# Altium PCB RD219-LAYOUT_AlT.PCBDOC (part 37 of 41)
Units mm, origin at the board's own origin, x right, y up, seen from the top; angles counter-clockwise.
Board outline 209.75 x 159.97 mm, 2 copper layers (TOP, BOTTOM), stack 0 mm thick; 398 components, 199 nets, 1469 pads, 0 vias.
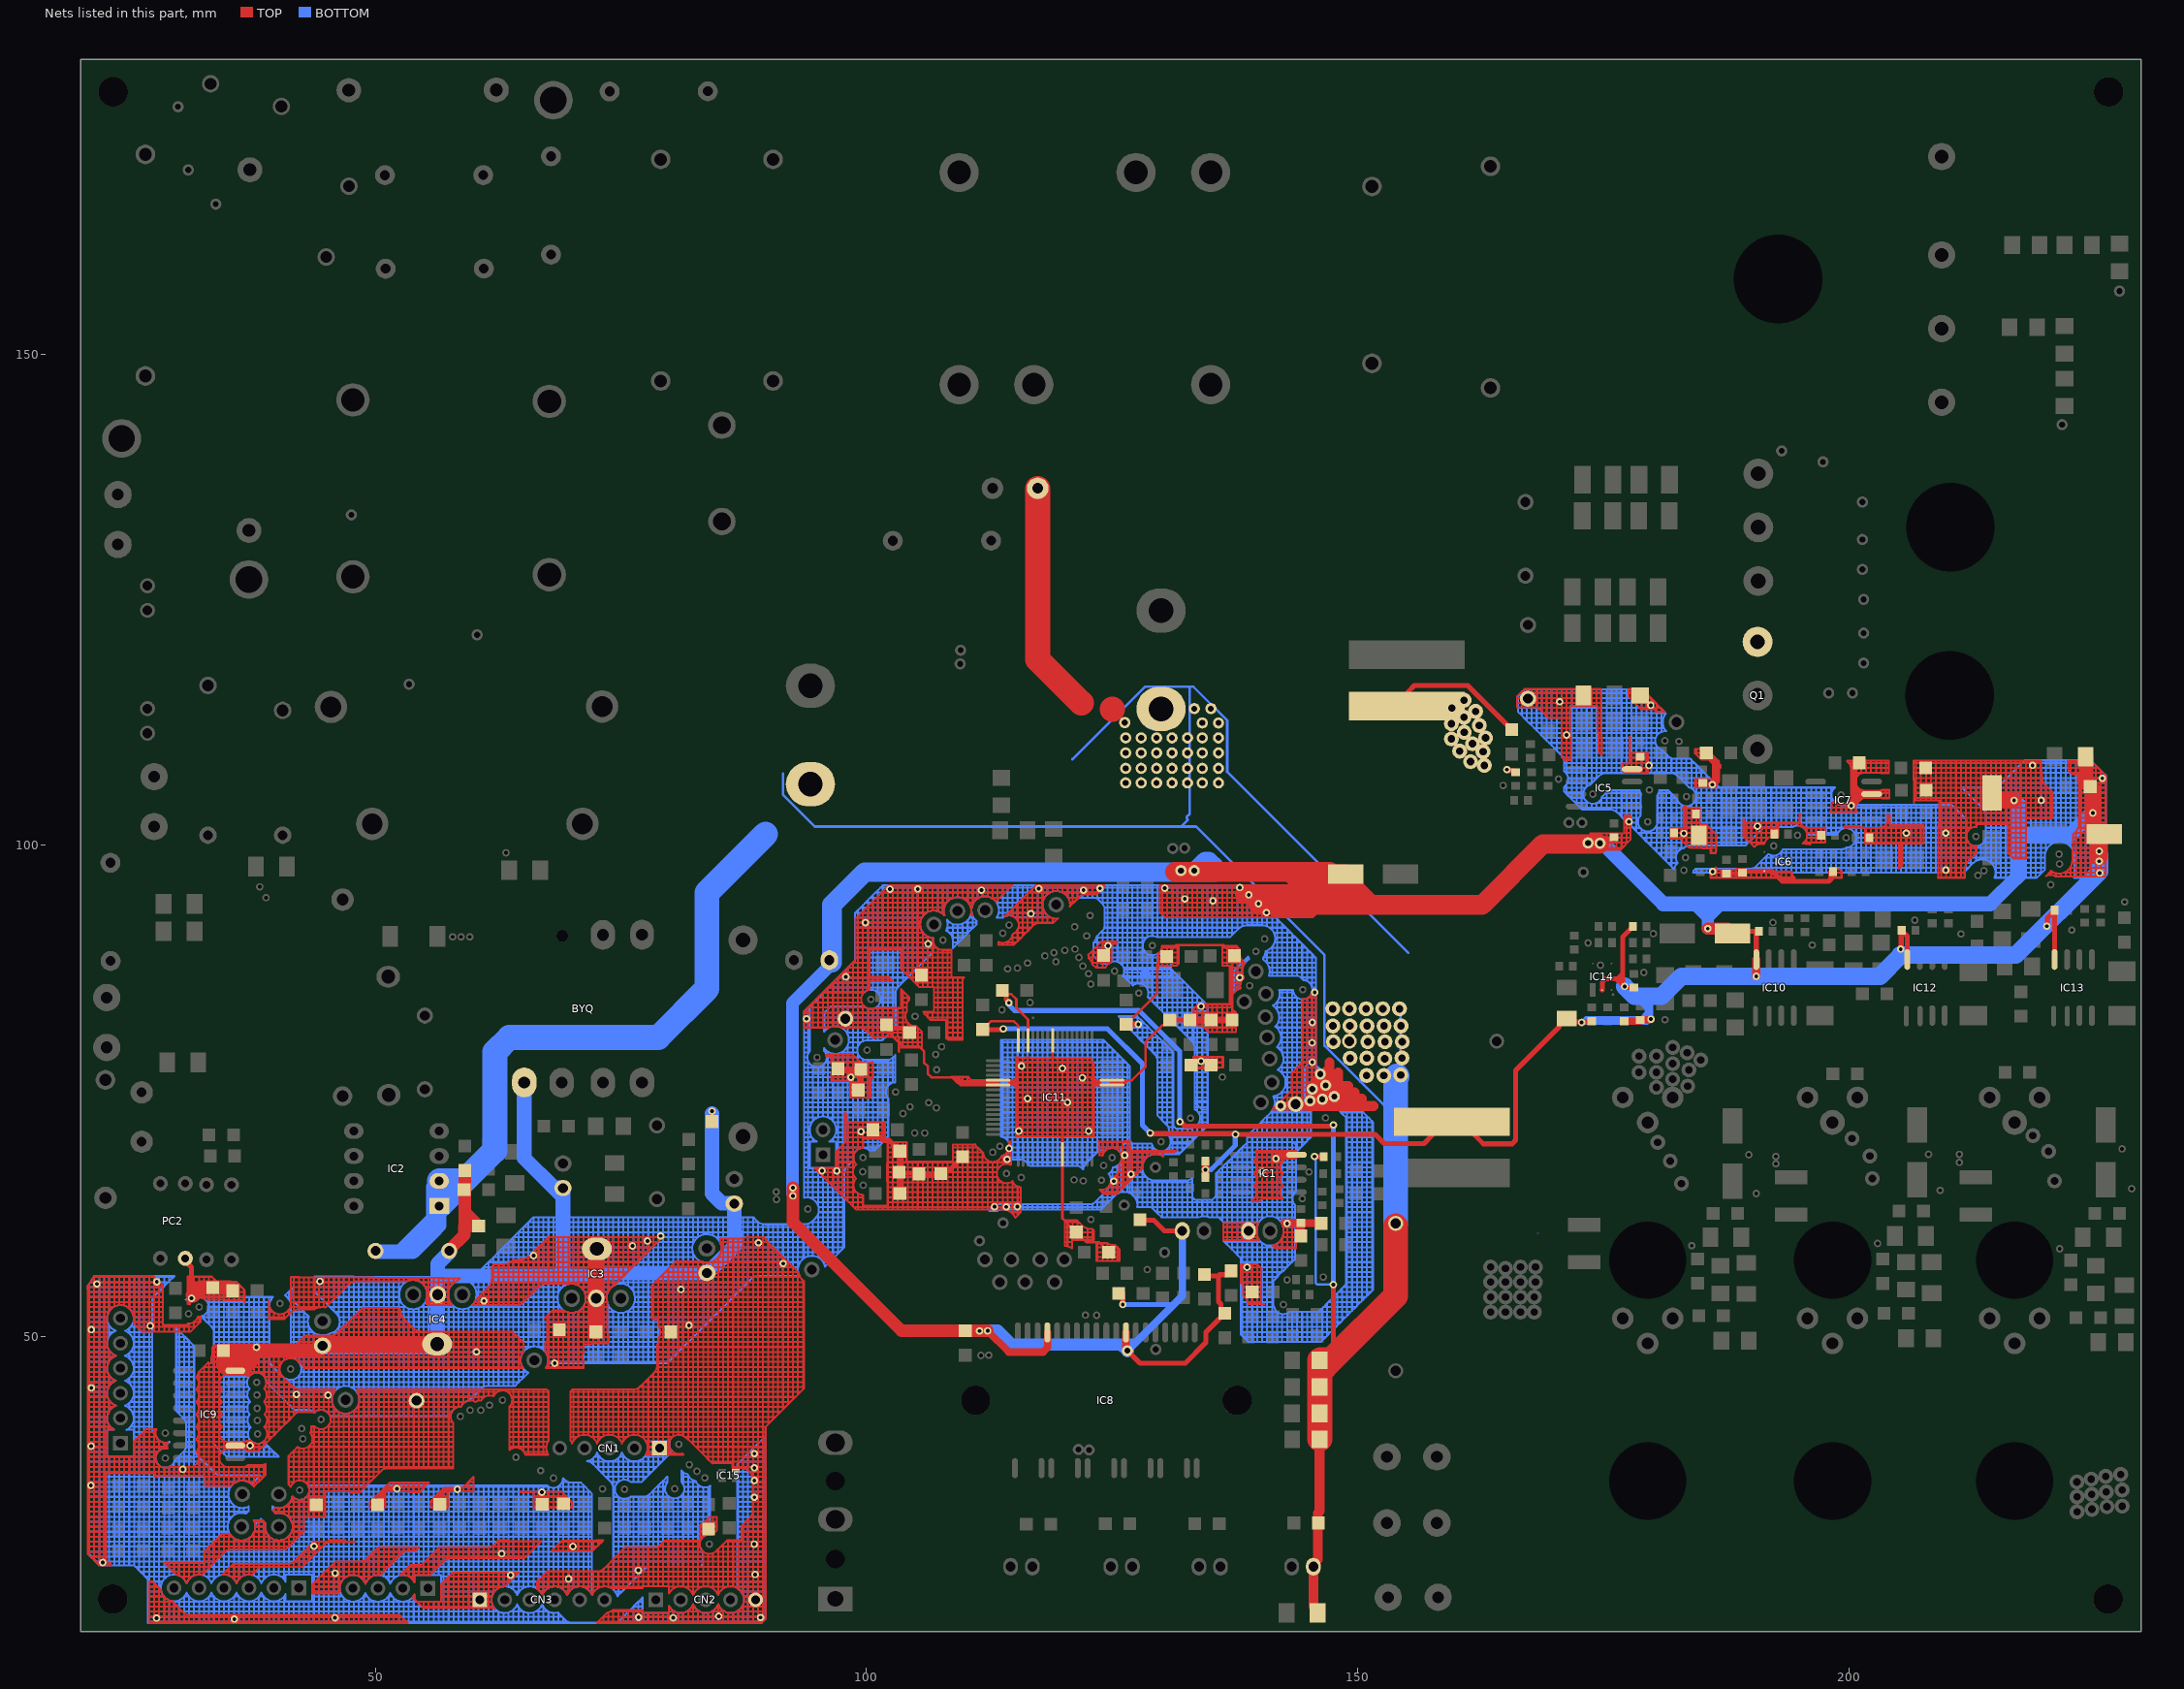
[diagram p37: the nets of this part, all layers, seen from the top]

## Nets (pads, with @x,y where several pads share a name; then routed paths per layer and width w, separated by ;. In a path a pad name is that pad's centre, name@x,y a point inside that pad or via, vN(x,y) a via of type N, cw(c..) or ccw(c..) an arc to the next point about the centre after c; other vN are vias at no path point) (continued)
GND: (continued)
  BOTTOM w0.203: 188.529,97.212 188.529,97.216 ; 188.529,97.212 189.037,97.212 ; 188.529,97.216 188.529,97.63 ; 188.529,97.216 189.037,97.216 ; 188.529,97.63 189.037,97.63 ; 188.529,99.977 188.529,100.264 ; 188.529,99.977 189.037,99.977 ; 188.529,100.264 188.529,100.772 ; 188.529,100.264 189.037,100.264 ; 188.529,100.772 188.529,101.28 ; 188.529,100.772 189.037,100.772 ; 188.529,101.28 188.529,101.788 ; 188.529,101.28 189.037,101.28 ; 188.529,101.788 188.529,102.296 ; 188.529,101.788 189.037,101.788 ; 188.529,102.296 188.529,102.804 ; 188.529,102.296 189.037,102.296 ; 188.529,102.804 188.529,103.312 ; 188.529,102.804 189.037,102.804 ; 188.529,103.312 188.529,103.82 ; 188.529,103.312 189.037,103.312 ; 188.529,103.82 188.529,104.328 ; 188.529,103.82 189.037,103.82 ; 188.529,104.328 188.529,104.836 ; 188.529,104.328 189.037,104.328 ; 188.529,104.836 188.529,105.344 ; 188.529,104.836 189.037,104.836 ; 188.529,105.344 188.529,105.852 ; 188.529,105.344 189.037,105.344 ; 188.529,105.852 188.529,105.886 ; 188.529,105.852 189.037,105.852 ; 188.529,105.886 189.037,105.886 ; 189.037,97.212 189.037,97.216 ; 189.037,97.212 189.545,97.212 ; 189.037,97.216 189.037,97.63 ; 189.037,97.216 189.545,97.216 ; 189.037,97.63 189.545,97.63 ; 189.037,99.977 189.037,100.264 ; 189.037,99.977 189.445,99.977 189.545,100.077 ; 189.037,100.264 189.037,100.772 ; 189.037,100.264 189.545,100.264 ; 189.037,100.772 189.037,101.28 ; 189.037,100.772 189.545,100.772 ; 189.037,101.28 189.037,101.788 ; 189.037,101.28 189.545,101.28 ; 189.037,101.788 189.037,102.296 ; 189.037,101.788 189.545,101.788 ; 189.037,102.296 189.545,102.296 ; 189.037,102.296 189.037,102.804 ; 189.037,102.804 189.545,102.804 ; 189.037,102.804 189.037,103.312 ; 189.037,103.312 189.037,103.82 ; 189.037,103.312 189.545,103.312 ; 189.037,103.82 189.037,104.328 ; 189.037,103.82 189.545,103.82 ; 189.037,104.328 189.545,104.328 ; 189.037,104.328 189.037,104.836 ; 189.037,104.836 189.545,104.836 ; 189.037,104.836 189.037,105.344 ; 189.037,105.344 189.037,105.852 ; 189.037,105.344 189.545,105.344 ; 189.037,105.852 189.545,105.852 ; 189.037,105.852 189.037,105.886 ; 189.037,105.886 189.545,105.886 ; 189.545,97.212 190.053,97.212 ; 189.545,97.212 189.545,97.216 ; 189.545,97.216 190.053,97.216 ; 189.545,97.216 189.545,97.63 ; 189.545,97.63 190.002,97.63 ; 189.545,100.077 189.732,100.264 ; 189.545,100.077 189.545,100.264 ; 189.545,100.264 189.545,100.772 ; 189.545,100.264 189.732,100.264 ; 189.545,100.772 189.545,101.28 ; 189.545,100.772 190.053,100.772 ; 189.545,101.28 189.545,101.788 ; 189.545,101.28 190.053,101.28 ; 189.545,101.788 189.545,102.296 ; 189.545,101.788 190.053,101.788 ; 189.545,102.296 189.545,102.804 ; 189.545,102.296 190.053,102.296 ; 189.545,102.804 189.545,103.312 ; 189.545,102.804 190.053,102.804 ; 189.545,103.312 189.545,103.82 ; 189.545,103.312 190.053,103.312 ; 189.545,103.82 189.545,104.328 ; 189.545,103.82 190.053,103.82 ; 189.545,104.328 190.053,104.328 ; 189.545,104.328 189.545,104.836 ; 189.545,104.836 190.053,104.836 ; 189.545,104.836 189.545,105.344 ; 189.545,105.344 189.545,105.852 ; 189.545,105.344 190.053,105.344 ; 189.545,105.852 190.053,105.852 ; 189.545,105.852 189.545,105.886 ; 189.545,105.886 190.053,105.886 ; 189.732,100.264 190.053,100.585 ; 190.002,97.63 ccw(c190.002,98.359) 190.053,97.632 ; 190.002,97.63 ccw(c190.002,98.359) 190.053,97.632 ; 190.053,97.212 190.053,97.216 ; 190.053,97.212 190.561,97.212 ; 190.053,97.216 190.561,97.216 ; 190.053,97.216 190.053,97.632 ; 190.053,97.632 ccw(c190.002,98.359) 190.359,97.724 ; 190.053,97.632 ccw(c190.002,98.359) 190.359,97.724 ; 190.053,100.585 190.24,100.772 ; 190.053,100.585 190.053,100.772 ; 190.053,100.772 190.053,101.28 ; 190.053,100.772 190.24,100.772 ; 190.053,101.28 190.053,101.788 ; 190.053,101.28 190.561,101.28 ; 190.053,101.788 190.053,102.296 ; 190.053,101.788 pad.@190.561,101.788 ; 190.053,102.296 190.053,102.804 ; 190.053,102.296 pad.@190.561,102.296 ; 190.053,102.804 190.053,103.312 ; 190.053,102.804 190.561,102.804 ; 190.053,103.312 190.053,103.82 ; 190.053,103.312 190.561,103.312 ; 190.053,103.82 190.053,104.328 ; 190.053,103.82 190.561,103.82 ; 190.053,104.328 190.053,104.836 ; 190.053,104.328 190.561,104.328 ; 190.053,104.836 190.053,105.344 ; 190.053,104.836 190.561,104.836 ; 190.053,105.344 190.053,105.852 ; 190.053,105.344 190.561,105.344 ; 190.053,105.852 190.053,105.886 ; 190.053,105.852 190.561,105.852 ; 190.053,105.886 190.561,105.886 ; 190.24,100.772 190.561,101.093 ; 190.359,97.724 ccw(c190.002,98.359) 190.517,97.844 ; 190.359,97.724 ccw(c190.002,98.359) 190.517,97.844 ; 190.359,97.724 190.561,97.724 ; 190.517,97.844 190.905,98.232 ; 190.561,97.212 190.561,97.216 ; 190.561,97.212 191.069,97.212 ; 190.561,97.216 190.561,97.724 ; 190.561,97.216 191.069,97.216 ; 190.561,97.724 191.069,97.724 ; 190.561,101.093 190.748,101.28 ; 190.561,101.093 190.561,101.28 ; 190.561,101.28 pad.@190.561,101.788 ; 190.561,101.28 190.748,101.28 ; pad.@190.561,101.788 191.069,101.788 ; pad.@190.561,101.788 pad.@190.561,102.296 ; pad.@190.561,102.296 190.561,102.804 ; pad.@190.561,102.296 191.069,102.296 ; 190.561,102.804 191.069,102.804 ; 190.561,102.804 190.561,103.312 ; 190.561,103.312 190.561,103.82 ; 190.561,103.312 191.069,103.312 ; 190.561,103.82 190.561,104.328 ; 190.561,103.82 191.069,103.82 ; 190.561,104.328 191.069,104.328 ; 190.561,104.328 190.561,104.836 ; 190.561,104.836 191.069,104.836 ; 190.561,104.836 190.561,105.344 ; 190.561,105.344 190.561,105.852 ; 190.561,105.344 191.069,105.344 ; 190.561,105.852 191.069,105.852 ; 190.561,105.852 190.561,105.886 ; 190.561,105.886 191.069,105.886 ; 190.748,101.28 191.069,101.601 ; 190.905,98.232 191.069,98.396 ; 190.905,98.232 191.069,98.232 ; 191.069,97.212 191.069,97.216 ; 191.069,97.212 191.577,97.212 ; 191.069,97.216 191.069,97.724 ; 191.069,97.216 191.577,97.216 ; 191.069,97.724 191.069,98.232 ; 191.069,97.724 191.577,97.724 ; 191.069,98.232 191.069,98.396 ; 191.069,98.232 191.577,98.232 ; 191.069,98.396 191.413,98.74 ; 191.069,101.601 191.069,101.788 ; 191.069,101.601 191.099,101.631 ; 191.069,101.788 191.315,101.788 ; 191.069,101.788 191.069,102.296 ; 191.069,102.296 191.069,102.804 ; 191.069,102.296 191.577,102.296 ; 191.069,102.804 191.069,103.312 ; 191.069,102.804 191.577,102.804 ; 191.069,103.312 191.069,103.82 ; 191.069,103.312 191.577,103.312 ; 191.069,103.82 191.069,104.328 ; 191.069,103.82 191.577,103.82 ; 191.069,104.328 191.577,104.328 ; 191.069,104.328 191.069,104.836 ; 191.069,104.836 191.577,104.836 ; 191.069,104.836 191.069,105.344 ; 191.069,105.344 191.069,105.852 ; 191.069,105.344 191.577,105.344 ; 191.069,105.852 191.577,105.852 ; 191.069,105.852 191.069,105.886 ; 191.069,105.886 191.577,105.886 ; 191.099,101.631 cw(c191.704,101.026) 191.315,101.788 ; 191.099,101.631 cw(c191.704,101.026) 191.315,101.788 ; 191.316,101.788 cw(c191.704,101.026) 191.577,101.872 ; 191.316,101.788 cw(c191.704,101.026) 191.577,101.872 ; 191.413,98.74 191.577,98.904 ; 191.413,98.74 191.577,98.74 ; 191.577,97.212 191.577,97.216 ; 191.577,97.212 192.085,97.212 ; 191.577,97.216 191.577,97.724 ; 191.577,97.216 192.085,97.216 ; 191.577,97.724 191.577,98.232 ; 191.577,97.724 192.085,97.724 ; 191.577,98.232 191.577,98.74 ; 191.577,98.232 192.085,98.232 ; 191.577,98.74 191.577,98.904 ; 191.577,98.74 192.085,98.74 ; 191.577,101.872 cw(c191.704,101.026) 191.704,101.882 ; 191.577,101.872 cw(c191.704,101.026) 191.704,101.882 ; 191.577,101.872 191.577,102.296 ; 191.577,102.296 191.577,102.804 ; 191.577,102.296 192.085,102.296 ; 191.577,102.804 191.577,103.312 ; 191.577,102.804 192.085,102.804 ; 191.577,103.312 191.577,103.82 ; 191.577,103.312 192.085,103.312 ; 191.577,103.82 191.577,104.328 ; 191.577,103.82 192.085,103.82 ; 191.577,104.328 192.085,104.328 ; 191.577,104.328 191.577,104.836 ; 191.577,104.836 192.085,104.836 ; 191.577,104.836 191.577,105.344 ; 191.577,105.344 191.577,105.852 ; 191.577,105.344 192.085,105.344 ; 191.577,105.852 192.085,105.852 ; 191.577,105.852 191.577,105.886 ; 191.577,105.886 192.085,105.886 ; 191.704,101.882 192.085,101.882 ; 192.085,97.212 192.085,97.216 ; 192.085,97.212 192.593,97.212 ; 192.085,97.216 192.085,97.724 ; 192.085,97.216 192.593,97.216 ; 192.085,97.724 192.085,98.232 ; 192.085,97.724 192.593,97.724 ; 192.085,98.232 192.085,98.74 ; 192.085,98.232 192.593,98.232 ; 192.085,98.74 192.593,98.74 ; 192.085,98.74 192.085,98.992 ; 192.085,98.992 ccw(c192.336,99.942) 192.59,98.993 ccw(c192.336,99.942) 192.593,98.994 ; 192.085,101.882 192.085,102.296 ; 192.085,101.882 192.593,101.882 ; 192.085,102.296 192.085,102.804 ; 192.085,102.296 192.593,102.296 ; 192.085,102.804 192.085,103.312 ; 192.085,102.804 192.593,102.804 ; 192.085,103.312 192.085,103.82 ; 192.085,103.312 192.593,103.312 ; 192.085,103.82 192.085,104.328 ; 192.085,103.82 192.593,103.82 ; 192.085,104.328 192.085,104.836 ; 192.085,104.328 192.593,104.328 ; 192.085,104.836 192.085,105.344 ; 192.085,104.836 192.593,104.836 ; 192.085,105.344 192.085,105.852 ; 192.085,105.344 192.593,105.344 ; 192.085,105.852 192.085,105.886 ; 192.085,105.852 192.593,105.852 ; 192.085,105.886 192.593,105.886 ; 192.593,97.212 192.593,97.216 ; 192.593,97.212 193.101,97.212 ; 192.593,97.216 192.593,97.724 ; 192.593,97.216 193.101,97.216 ; 192.593,97.724 192.593,98.232 ; 192.593,97.724 193.101,97.724 ; 192.593,98.232 192.593,98.74 ; 192.593,98.232 193.101,98.232 ; 192.593,98.74 193.101,98.74 ; 192.593,98.74 192.593,98.994 ; 192.593,98.994 ccw(c192.336,99.942) 193.031,99.248 ; 192.593,101.882 192.593,102.296 ; 192.593,101.882 193.101,101.882 ; 192.593,102.296 192.593,102.804 ; 192.593,102.296 193.101,102.296 ; 192.593,102.804 192.593,103.312 ; 192.593,102.804 193.101,102.804 ; 192.593,103.312 192.593,103.82 ; 192.593,103.312 193.101,103.312 ; 192.593,103.82 192.593,104.328 ; 192.593,103.82 193.101,103.82 ; 192.593,104.328 192.593,104.836 ; 192.593,104.328 193.101,104.328 ; 192.593,104.836 192.593,105.344 ; 192.593,104.836 193.101,104.836 ; 192.593,105.344 192.593,105.852 ; 192.593,105.344 193.101,105.344 ; 192.593,105.852 192.593,105.886 ; 192.593,105.852 193.101,105.852 ; 192.593,105.886 193.101,105.886 ; 193.031,99.248 ccw(c192.336,99.942) 193.099,99.324 ccw(c192.336,99.942) 193.101,99.326 ; 193.031,99.248 193.101,99.248 ; 193.101,97.212 193.101,97.216 ; 193.101,97.212 193.609,97.212 ; 193.101,97.216 193.101,97.724 ; 193.101,97.216 193.609,97.216 ; 193.101,97.724 193.101,98.232 ; 193.101,97.724 193.609,97.724 ; 193.101,98.232 193.101,98.74 ; 193.101,98.232 193.609,98.232 ; 193.101,98.74 193.101,99.248 ; 193.101,98.74 193.609,98.74 ; 193.101,99.248 193.609,99.248 ; 193.101,99.248 193.101,99.326 ; 193.101,101.882 193.101,102.296 ; 193.101,101.882 193.609,101.882 ; 193.101,102.296 193.101,102.804 ; 193.101,102.296 193.609,102.296 ; 193.101,102.804 193.101,103.312 ; 193.101,102.804 193.609,102.804 ; 193.101,103.312 193.101,103.82 ; 193.101,103.312 193.609,103.312 ; 193.101,103.82 193.101,104.328 ; 193.101,103.82 193.609,103.82 ; 193.101,104.328 193.101,104.836 ; 193.101,104.328 193.609,104.328 ; 193.101,104.836 193.101,105.344 ; 193.101,104.836 193.609,104.836 ; 193.101,105.344 193.101,105.852 ; 193.101,105.344 193.609,105.344 ; 193.101,105.852 193.101,105.886 ; 193.101,105.852 193.609,105.852 ; 193.101,105.886 193.609,105.886 ; 193.609,97.212 193.609,97.216 ; 193.609,97.212 194.117,97.212 ; 193.609,97.216 193.609,97.724 ; 193.609,97.216 194.117,97.216 ; 193.609,97.724 193.609,98.232 ; 193.609,97.724 194.117,97.724 ; 193.609,98.232 193.609,98.74 ; 193.609,98.232 194.117,98.232 ; 193.609,98.74 193.609,99.248 ; 193.609,98.74 194.117,98.74 ; 193.609,99.248 193.609,99.613 ; 193.609,99.248 194.117,99.248 ; 193.609,99.613 194.117,99.613 ; 193.609,101.882 194.117,101.882 ; 193.609,101.882 193.609,102.296 ; 193.609,102.296 194.117,102.296 ; 193.609,102.296 193.609,102.804 ; 193.609,102.804 194.117,102.804 ; 193.609,102.804 193.609,103.312 ; 193.609,103.312 193.609,103.82 ; 193.609,103.312 194.117,103.312 ; 193.609,103.82 193.609,104.328 ; 193.609,103.82 194.117,103.82 ; 193.609,104.328 194.117,104.328 ; 193.609,104.328 193.609,104.836 ; 193.609,104.836 194.117,104.836 ; 193.609,104.836 193.609,105.344 ; 193.609,105.344 193.609,105.852 ; 193.609,105.344 194.117,105.344 ; 193.609,105.852 194.117,105.852 ; 193.609,105.852 193.609,105.886 ; 193.609,105.886 194.117,105.886 ; 194.117,97.212 194.117,97.216 ; 194.117,97.212 194.625,97.212 ; 194.117,97.216 194.117,97.724 ; 194.117,97.216 194.625,97.216 ; 194.117,97.724 194.117,98.232 ; 194.117,97.724 194.625,97.724 ; 194.117,98.232 194.117,98.74 ; 194.117,98.232 194.625,98.232 ; 194.117,98.74 194.117,99.248 ; 194.117,98.74 194.625,98.74 ; 194.117,99.248 194.117,99.613 ; 194.117,99.248 194.625,99.248 ; 194.117,99.613 194.625,99.613 ; 194.117,101.882 194.117,102.296 ; 194.117,102.296 194.117,102.804 ; 194.117,102.296 194.625,102.296 ; 194.117,102.804 194.117,103.312 ; 194.117,102.804 194.625,102.804 ; 194.117,103.312 194.117,103.82 ; 194.117,103.312 194.625,103.312 ; 194.117,103.82 194.117,104.328 ; 194.117,103.82 194.625,103.82 ; 194.117,104.328 194.625,104.328 ; 194.117,104.328 194.117,104.836 ; 194.117,104.836 194.625,104.836 ; 194.117,104.836 194.117,105.344 ; 194.117,105.344 194.117,105.852 ; 194.117,105.344 194.625,105.344 ; 194.117,105.852 194.625,105.852 ; 194.117,105.852 194.117,105.886 ; 194.117,105.886 194.625,105.886 ; 194.625,97.212 194.625,97.216 ; 194.625,97.212 195.133,97.212 ; 194.625,97.216 194.625,97.724 ; 194.625,97.216 195.133,97.216 ; 194.625,97.724 194.625,98.232 ; 194.625,97.724 195.133,97.724 ; 194.625,98.232 194.625,98.74 ; 194.625,98.232 195.133,98.232 ; 194.625,98.74 194.625,99.248 ; 194.625,98.74 195.133,98.74 ; 194.625,99.248 194.625,99.613 ; 194.625,99.248 195.133,99.248 ; 194.625,99.613 195.133,99.613 ; 194.625,102 cw(c194.752,101.026) 194.632,102.001 cw(c194.752,101.026) 195.133,101.932 ; 194.625,102 194.625,102.296 ; 194.625,102.296 194.625,102.804 ; 194.625,102.296 195.133,102.296 ; 194.625,102.804 194.625,103.312 ; 194.625,102.804 195.133,102.804 ; 194.625,103.312 194.625,103.82 ; 194.625,103.312 195.133,103.312 ; 194.625,103.82 194.625,104.328 ; 194.625,103.82 195.133,103.82 ; 194.625,104.328 194.625,104.836 ; 194.625,104.328 195.133,104.328 ; 194.625,104.836 194.625,105.344 ; 194.625,104.836 195.133,104.836 ; 194.625,105.344 194.625,105.852 ; 194.625,105.344 195.133,105.344 ; 194.625,105.852 194.625,105.886 ; 194.625,105.852 195.133,105.852 ; 194.625,105.886 195.133,105.886 ; 195.133,97.212 195.133,97.216 ; 195.133,97.212 195.641,97.212 ; 195.133,97.216 195.133,97.724 ; 195.133,97.216 195.641,97.216 ; 195.133,97.724 195.133,98.232 ; 195.133,97.724 195.641,97.724 ; 195.133,98.232 195.133,98.74 ; 195.133,98.232 195.641,98.232 ; 195.133,98.74 195.133,99.248 ; 195.133,98.74 195.641,98.74 ; 195.133,99.248 195.133,99.613 ; 195.133,99.248 195.641,99.248 ; 195.133,99.613 195.641,99.613 ; 195.133,101.932 cw(c194.752,101.026) 195.136,101.93 cw(c194.752,101.026) 195.37,101.79 cw(c194.752,101.026) 195.372,101.788 ; 195.133,101.932 195.133,102.296 ; 195.133,102.296 195.133,102.804 ; 195.133,102.296 195.641,102.296 ; 195.133,102.804 195.133,103.312 ; 195.133,102.804 195.641,102.804 ; 195.133,103.312 195.133,103.82 ; 195.133,103.312 195.641,103.312 ; 195.133,103.82 195.133,104.328 ; 195.133,103.82 195.641,103.82 ; 195.133,104.328 195.133,104.836 ; 195.133,104.328 195.641,104.328 ; 195.133,104.836 195.133,105.344 ; 195.133,104.836 195.641,104.836 ; 195.133,105.344 195.133,105.852 ; 195.133,105.344 195.641,105.344 ; 195.133,105.852 195.133,105.886 ; 195.133,105.852 195.641,105.852 ; 195.133,105.886 195.641,105.886 ; 195.372,101.788 cw(c194.752,101.026) 195.641,101.445 ; 195.372,101.788 195.641,101.788 ; 195.641,97.212 195.641,97.216 ; 195.641,97.212 196.149,97.212 ; 195.641,97.216 195.641,97.724 ; 195.641,97.216 196.149,97.216 ; 195.641,97.724 195.641,98.232 ; 195.641,97.724 196.149,97.724 ; 195.641,98.232 195.641,98.74 ; 195.641,98.232 196.149,98.232 ; 195.641,98.74 195.641,99.248 ; 195.641,98.74 196.149,98.74 ; 195.641,99.248 195.641,99.613 ; 195.641,99.248 196.149,99.248 ; 195.641,99.613 196.149,99.613 ; 195.641,101.445 cw(c194.752,101.026) 195.701,101.28 ; 195.641,101.445 195.641,101.788 ; 195.641,101.788 195.641,102.296 ; 195.641,101.788 196.149,101.788 ; 195.641,102.296 195.641,102.804 ; 195.641,102.296 196.149,102.296 ; 195.641,102.804 195.641,103.312 ; 195.641,102.804 196.149,102.804 ; 195.641,103.312 195.641,103.82 ; 195.641,103.312 196.149,103.312 ; 195.641,103.82 195.641,104.328 ; 195.641,103.82 196.149,103.82 ; 195.641,104.328 195.641,104.836 ; 195.641,104.328 196.149,104.328 ; 195.641,104.836 195.641,105.344 ; 195.641,104.836 196.149,104.836 ; 195.641,105.344 195.641,105.852 ; 195.641,105.344 196.149,105.344 ; 195.641,105.852 195.641,105.886 ; 195.641,105.852 196.149,105.852 ; 195.641,105.886 196.149,105.886 ; 195.701,101.28 196.149,101.28 ; 196.149,97.212 196.149,97.216 ; 196.149,97.212 196.657,97.212 ; 196.149,97.216 196.149,97.724 ; 196.149,97.216 196.657,97.216 ; 196.149,97.724 196.149,98.232 ; 196.149,97.724 196.657,97.724 ; 196.149,98.232 196.149,98.74 ; 196.149,98.232 196.657,98.232 ; 196.149,98.74 196.149,99.248 ; 196.149,98.74 196.657,98.74 ; 196.149,99.248 196.149,99.613 ; 196.149,99.248 196.657,99.248 ; 196.149,99.613 196.657,99.613 ; 196.149,101.071 196.149,101.28 ; 196.149,101.071 196.657,101.071 ; 196.149,101.28 196.149,101.788 ; 196.149,101.28 196.657,101.28 ; 196.149,101.788 196.149,102.296 ; 196.149,101.788 196.657,101.788 ; 196.149,102.296 196.149,102.804 ; 196.149,102.296 196.657,102.296 ; 196.149,102.804 196.149,103.312 ; 196.149,102.804 196.657,102.804 ; 196.149,103.312 196.149,103.82 ; 196.149,103.312 196.657,103.312 ; 196.149,103.82 196.149,104.328 ; 196.149,103.82 196.657,103.82 ; 196.149,104.328 196.149,104.836 ; 196.149,104.328 196.657,104.328 ; 196.149,104.836 196.149,105.344 ; 196.149,104.836 196.657,104.836 ; 196.149,105.344 196.149,105.852 ; 196.149,105.344 196.657,105.344 ; 196.149,105.852 196.149,105.886 ; 196.149,105.852 196.657,105.852 ; 196.149,105.886 196.657,105.886 ; 196.657,97.212 196.657,97.216 ; 196.657,97.212 197.165,97.212 ; 196.657,97.216 196.657,97.724 ; 196.657,97.216 197.165,97.216 ; 196.657,97.724 196.657,98.232 ; 196.657,97.724 197.165,97.724 ; 196.657,98.232 196.657,98.74 ; 196.657,98.232 197.165,98.232 ; 196.657,98.74 196.657,99.248 ; 196.657,98.74 197.165,98.74 ; 196.657,99.248 196.657,99.613 ; 196.657,99.248 197.165,99.248 ; 196.657,99.613 197.165,99.613 ; 196.657,101.071 196.657,101.28 ; 196.657,101.071 197.165,101.071 ; 196.657,101.28 196.657,101.788 ; 196.657,101.28 197.165,101.28 ; 196.657,101.788 196.657,102.296 ; 196.657,101.788 197.165,101.788 ; 196.657,102.296 196.657,102.804 ; 196.657,102.296 197.165,102.296 ; 196.657,102.804 196.657,103.312 ; 196.657,102.804 197.165,102.804 ; 196.657,103.312 196.657,103.82 ; 196.657,103.312 197.165,103.312 ; 196.657,103.82 196.657,104.328 ; 196.657,103.82 197.165,103.82 ; 196.657,104.328 196.657,104.836 ; 196.657,104.328 197.165,104.328 ; 196.657,104.836 196.657,105.344 ; 196.657,104.836 197.165,104.836 ; 196.657,105.344 196.657,105.852 ; 196.657,105.344 197.165,105.344 ; 196.657,105.852 196.657,105.886 ; 196.657,105.852 197.165,105.852 ; 196.657,105.886 197.165,105.886 ; 197.165,97.212 197.165,97.216 ; 197.165,97.212 197.673,97.212 ; 197.165,97.216 197.165,97.724 ; 197.165,97.216 197.673,97.216 ; 197.165,97.724 197.165,98.232 ; 197.165,97.724 197.673,97.724 ; 197.165,98.232 197.165,98.74 ; 197.165,98.232 197.673,98.232 ; 197.165,98.74 197.165,99.248 ; 197.165,98.74 197.673,98.74 ; 197.165,99.248 197.165,99.613 ; 197.165,99.248 197.673,99.248 ; 197.165,99.613 197.673,99.613 ; 197.165,101.071 197.165,101.28 ; 197.165,101.071 197.673,101.071 ; 197.165,101.28 197.165,101.788 ; 197.165,101.28 197.673,101.28 ; 197.165,101.788 197.165,102.296 ; 197.165,101.788 197.673,101.788 ; 197.165,102.296 197.165,102.804 ; 197.165,102.296 197.673,102.296 ; 197.165,102.804 197.165,103.312 ; 197.165,102.804 197.673,102.804 ; 197.165,103.312 197.165,103.82 ; 197.165,103.312 197.673,103.312 ; 197.165,103.82 197.165,104.328 ; 197.165,103.82 197.673,103.82 ; 197.165,104.328 197.165,104.836 ; 197.165,104.328 197.673,104.328 ; 197.165,104.836 197.165,105.344 ; 197.165,104.836 197.673,104.836 ; 197.165,105.344 197.165,105.852 ; 197.165,105.344 197.673,105.344 ; 197.165,105.852 197.165,105.886 ; 197.165,105.852 197.673,105.852 ; 197.165,105.886 197.673,105.886 ; 197.673,97.212 197.673,97.216 ; 197.673,97.212 198.181,97.212 ; 197.673,97.216 197.673,97.724 ; 197.673,97.216 198.181,97.216 ; 197.673,97.724 197.673,98.232 ; 197.673,97.724 198.181,97.724 ; 197.673,98.232 197.673,98.74 ; 197.673,98.232 198.181,98.232 ; 197.673,98.74 197.673,99.248 ; 197.673,98.74 198.181,98.74 ; 197.673,99.248 197.673,99.613 ; 197.673,99.248 198.181,99.248 ; 197.673,99.613 198.181,99.613 ; 197.673,101.071 197.673,101.28 ; 197.673,101.071 198.181,101.071 ; 197.673,101.28 197.673,101.788 ; 197.673,101.28 198.181,101.28 ; 197.673,101.788 197.673,102.296 ; 197.673,101.788 198.181,101.788 ; 197.673,102.296 197.673,102.804 ; 197.673,102.296 198.181,102.296 ; 197.673,102.804 197.673,103.312 ; 197.673,102.804 198.181,102.804 ; 197.673,103.312 197.673,103.82 ; 197.673,103.312 198.181,103.312 ; 197.673,103.82 197.673,104.328 ; 197.673,103.82 198.181,103.82 ; 197.673,104.328 197.673,104.836 ; 197.673,104.328 198.181,104.328 ; 197.673,104.836 197.673,105.344 ; 197.673,104.836 198.181,104.836 ; 197.673,105.344 197.673,105.852 ; 197.673,105.344 198.181,105.344 ; 197.673,105.852 197.673,105.886 ; 197.673,105.852 198.181,105.852 ; 197.673,105.886 198.181,105.886 ; 198.181,97.212 198.181,97.216 ; 198.181,97.212 198.689,97.212 ; 198.181,97.216 198.181,97.724 ; 198.181,97.216 198.689,97.216 ; 198.181,97.724 198.181,98.232 ; 198.181,97.724 198.689,97.724 ; 198.181,98.232 198.181,98.74 ; 198.181,98.232 198.689,98.232 ; 198.181,98.74 198.181,99.248 ; 198.181,98.74 198.689,98.74 ; 198.181,99.248 198.181,99.613 ; 198.181,99.248 198.689,99.248 ; 198.181,99.613 198.689,99.613 ; 198.181,101.071 198.689,101.071 ; 198.181,101.071 198.181,101.28 ; 198.181,101.28 198.181,101.788 ; 198.181,101.28 198.689,101.28 ; 198.181,101.788 198.181,102.296 ; 198.181,101.788 198.689,101.788 ; 198.181,102.296 198.689,102.296 ; 198.181,102.296 198.181,102.804 ; 198.181,102.804 198.689,102.804 ; 198.181,102.804 198.181,103.312 ; 198.181,103.312 198.181,103.82 ; 198.181,103.312 198.689,103.312 ; 198.181,103.82 198.181,104.328 ; 198.181,103.82 198.689,103.82 ; 198.181,104.328 198.181,104.836 ; 198.181,104.328 198.608,104.328 ; 198.181,104.836 198.181,105.344 ; 198.181,104.836 198.251,104.836 ; 198.181,105.344 198.181,105.852 ; 198.181,105.344 198.229,105.344 ; 198.181,105.852 198.181,105.886 ; 198.181,105.852 198.522,105.852 ; 198.229,105.344 ccw(c199.188,105.13) 198.251,104.836 ; 198.229,105.344 ccw(c199.188,105.13) 198.206,105.13 ccw(c199.188,105.13) 198.251,104.836 ; 198.229,105.344 ccw(c199.188,105.13) 198.227,105.334 cw(c199.188,105.13) 198.229,105.344 ; 198.229,105.344 cw(c199.188,105.13) 198.522,105.852 ; 198.229,105.344 cw(c199.188,105.13) 198.231,105.351 ccw(c199.188,105.13) 198.229,105.344 ; 198.229,105.344 cw(c199.188,105.13) 198.522,105.852 ; 198.251,104.836 ccw(c199.188,105.13) 198.494,104.435 cw(c199.188,105.13) 198.251,104.836 ; 198.522,105.852 cw(c199.188,105.13) 198.557,105.882 ccw(c199.188,105.13) 198.522,105.852 ; 198.608,104.328 ccw(c199.228,105.09) 198.689,104.269 ; 198.608,104.328 ccw(c199.228,105.09) 198.689,104.269 ; 198.608,104.328 cw(c199.228,105.09) 198.533,104.395 ccw(c199.228,105.09) 198.608,104.328 ; 198.689,97.212 199.197,97.212 ; 198.689,97.212 198.689,97.216 ; 198.689,97.216 199.197,97.216 ; 198.689,97.216 198.689,97.724 ; 198.689,97.724 199.197,97.724 ; 198.689,97.724 198.689,98.232 ; 198.689,98.232 199.197,98.232 ; 198.689,98.232 198.689,98.74 ; 198.689,98.74 199.197,98.74 ; 198.689,98.74 198.689,99.248 ; 198.689,99.248 198.689,99.613 ; 198.689,99.248 199.197,99.248 ; 198.689,99.613 199.197,99.613 ; 198.689,101.071 198.689,101.28 ; 198.689,101.28 198.689,101.788 ; 198.689,101.28 198.864,101.28 ; 198.689,101.788 198.689,102.296 ; 198.689,101.788 199.197,101.788 ; 198.689,102.296 198.689,102.804 ; 198.689,102.296 199.197,102.296 ; 198.689,102.804 198.689,103.312 ; 198.689,102.804 199.197,102.804 ; 198.689,103.312 198.689,103.82 ; 198.689,103.312 199.197,103.312 ; 198.689,103.82 199.197,103.82 ; 198.689,103.82 198.689,104.269 ; 198.689,104.269 ccw(c199.228,105.09) 199.197,104.108 ; 198.689,104.269 ccw(c199.228,105.09) 199.197,104.108 ; 198.864,101.28 cw(c199.705,100.772) 199.197,101.613 ; 199.197,97.212 199.197,97.216 ; 199.197,97.212 199.705,97.212 ; 199.197,97.216 199.197,97.724 ; 199.197,97.216 199.705,97.216 ; 199.197,97.724 199.197,98.232 ; 199.197,97.724 199.705,97.724 ; 199.197,98.232 199.197,98.74 ; 199.197,98.232 199.705,98.232 ; 199.197,98.74 199.705,98.74 ; 199.197,98.74 199.197,99.248 ; 199.197,99.248 199.197,99.613 ; 199.197,99.248 199.705,99.248 ; 199.197,99.613 199.275,99.613 ; 199.197,101.613 cw(c199.705,100.772) 199.705,101.755 ; 199.197,101.613 199.197,101.788 ; 199.197,101.788 199.197,102.296 ; 199.197,101.788 199.705,101.788 ; 199.197,102.296 199.197,102.804 ; 199.197,102.296 199.705,102.296 ; 199.197,102.804 199.197,103.312 ; 199.197,102.804 199.705,102.804 ; 199.197,103.312 199.197,103.82 ; 199.197,103.312 199.705,103.312 ; 199.197,103.82 199.705,103.82 ; 199.197,103.82 199.197,104.108 ; 199.197,104.108 ccw(c199.228,105.09) 199.228,104.107 ; 199.197,104.108 ccw(c199.228,105.09) 199.228,104.107 ; 199.228,104.107 199.705,104.107 ; 199.275,99.613 ccw(c199.275,100.342) 199.705,99.754 ; 199.275,99.613 ccw(c199.275,100.342) 199.705,99.754 ; 199.705,97.212 199.705,97.216 ; 199.705,97.212 200.213,97.212 ; 199.705,97.216 199.705,97.724 ; 199.705,97.216 200.213,97.216 ; 199.705,97.724 199.705,98.232 ; 199.705,97.724 200.213,97.724 ; 199.705,98.232 199.705,98.74 ; 199.705,98.232 200.213,98.232 ; 199.705,98.74 199.705,99.248 ; 199.705,98.74 200.213,98.74 ; 199.705,99.248 200.213,99.248 ; 199.705,99.248 199.705,99.754 ; 199.705,99.754 ccw(c199.275,100.342) 199.708,99.756 ; 199.705,99.754 ccw(c199.275,100.342) 199.708,99.756 ; 199.705,101.755 199.705,101.788 ; 199.705,101.788 199.705,102.296 ; 199.705,101.788 200.213,101.788 ; 199.705,102.296 199.705,102.804 ; 199.705,102.296 200.213,102.296 ; 199.705,102.804 199.705,103.312 ; 199.705,102.804 200.213,102.804 ; 199.705,103.312 199.705,103.82 ; 199.705,103.312 200.213,103.312 ; 199.705,103.82 199.705,104.107 ; 199.705,103.82 pad.@200.213,103.82 ; 199.705,104.107 pad.@200.213,104.107 ; 199.708,99.756 ccw(c199.275,100.342) 199.753,99.792 cw(c199.275,100.342) 199.708,99.756 ; 199.708,99.756 200.213,99.756 ; 200.213,97.212 200.213,97.216 ; 200.213,97.212 200.721,97.212 ; 200.213,97.216 200.213,97.724 ; 200.213,97.216 200.721,97.216 ; 200.213,97.724 200.213,98.232 ; 200.213,97.724 200.721,97.724 ; 200.213,98.232 200.213,98.74 ; 200.213,98.232 200.721,98.232 ; 200.213,98.74 200.213,99.248 ; 200.213,98.74 200.721,98.74 ; 200.213,99.248 200.213,99.756 ; 200.213,99.248 200.721,99.248 ; 200.213,99.756 200.721,99.756 ; 200.213,99.756 200.213,99.931 ; 200.213,99.931 ccw(c199.705,100.772) 200.546,100.264 ; 200.213,101.613 cw(c199.705,100.772) 200.546,101.28 ; 200.213,101.613 200.213,101.788 ; 200.213,101.788 200.213,102.296 ; 200.213,101.788 200.721,101.788 ; 200.213,102.296 200.213,102.804 ; 200.213,102.296 200.721,102.296 ; 200.213,102.804 200.213,103.312 ; 200.213,102.804 200.721,102.804 ; 200.213,103.312 pad.@200.213,103.82 ; 200.213,103.312 200.721,103.312 ; pad.@200.213,103.82 pad.@200.213,104.107 ; pad.@200.213,103.82 200.721,103.82 ; pad.@200.213,104.107 200.721,104.107 ; 200.546,100.264 ccw(c199.705,100.772) 200.547,100.266 ccw(c199.705,100.772) 200.688,100.772 ; 200.546,100.264 200.721,100.264 ; 200.546,101.28 200.721,101.28 ; 200.688,100.772 200.721,100.772 ; 200.721,97.212 200.721,97.216 ; 200.721,97.212 201.229,97.212 ; 200.721,97.216 200.721,97.724 ; 200.721,97.216 201.229,97.216 ; 200.721,97.724 200.721,98.232 ; 200.721,97.724 201.229,97.724 ; 200.721,98.232 200.721,98.74 ; 200.721,98.232 201.229,98.232 ; 200.721,98.74 200.721,99.248 ; 200.721,98.74 201.229,98.74 ; 200.721,99.248 200.721,99.756 ; 200.721,99.248 201.229,99.248 ; 200.721,99.756 200.721,100.264 ; 200.721,99.756 201.229,99.756 ; 200.721,100.264 200.721,100.772 ; 200.721,100.264 201.229,100.264 ; 200.721,100.772 200.721,101.28 ; 200.721,100.772 201.229,100.772 ; 200.721,101.28 200.721,101.788 ; 200.721,101.28 201.229,101.28 ; 200.721,101.788 200.721,102.296 ; 200.721,101.788 201.229,101.788 ; 200.721,102.296 200.721,102.804 ; 200.721,102.296 201.229,102.296 ; 200.721,102.804 200.721,103.312 ; 200.721,102.804 201.229,102.804 ; 200.721,103.312 200.721,103.82 ; 200.721,103.312 201.229,103.312 ; 200.721,103.82 200.721,104.107 ; 200.721,103.82 201.229,103.82 ; 200.721,104.107 201.229,104.107 ; 201.229,97.212 201.229,97.216 ; 201.229,97.212 201.737,97.212 ; 201.229,97.216 201.229,97.724 ; 201.229,97.216 201.737,97.216 ; 201.229,97.724 201.229,98.232 ; 201.229,97.724 201.737,97.724 ; 201.229,98.232 201.229,98.74 ; 201.229,98.232 201.737,98.232 ; 201.229,98.74 201.229,99.248 ; 201.229,98.74 201.737,98.74 ; 201.229,99.248 201.229,99.756 ; 201.229,99.248 201.737,99.248 ; 201.229,99.756 201.229,100.264 ; 201.229,99.756 201.737,99.756 ; 201.229,100.264 201.229,100.772 ; 201.229,100.264 201.737,100.264 ; 201.229,100.772 201.229,101.28 ; 201.229,100.772 201.737,100.772 ; 201.229,101.28 201.229,101.788 ; 201.229,101.28 201.737,101.28 ; 201.229,101.788 201.229,102.296 ; 201.229,101.788 201.737,101.788 ; 201.229,102.296 201.229,102.804 ; 201.229,102.296 201.737,102.296 ; 201.229,102.804 201.229,103.312 ; 201.229,102.804 201.737,102.804 ; 201.229,103.312 201.229,103.82 ; 201.229,103.312 201.737,103.312 ; 201.229,103.82 201.229,104.107 ; 201.229,103.82 201.737,103.82 ; 201.229,104.107 201.737,104.107 ; 201.737,97.212 201.737,97.216 ; 201.737,97.212 202.245,97.212 ; 201.737,97.216 201.737,97.724 ; 201.737,97.216 202.245,97.216 ; 201.737,97.724 201.737,98.232 ; 201.737,97.724 202.245,97.724 ; 201.737,98.232 201.737,98.74 ; 201.737,98.232 202.245,98.232 ; 201.737,98.74 201.737,99.248 ; 201.737,98.74 202.245,98.74 ; 201.737,99.248 201.737,99.756 ; 201.737,99.248 202.245,99.248 ; 201.737,99.756 201.737,100.264 ; 201.737,99.756 202.245,99.756 ; 201.737,100.264 201.737,100.772 ; 201.737,100.264 202.245,100.264 ; 201.737,100.772 201.737,101.28 ; 201.737,100.772 202.245,100.772 ; 201.737,101.28 201.737,101.788 ; 201.737,101.28 202.245,101.28 ; 201.737,101.788 201.737,102.296 ; 201.737,101.788 202.245,101.788 ; 201.737,102.296 201.737,102.804 ; 201.737,102.296 202.245,102.296 ; 201.737,102.804 201.737,103.312 ; 201.737,102.804 202.245,102.804 ; 201.737,103.312 201.737,103.82 ; 201.737,103.312 202.245,103.312 ; 201.737,103.82 201.737,104.107 ; 201.737,103.82 202.245,103.82 ; 201.737,104.107 202.245,104.107 ; 202.245,97.212 202.245,97.216 ; 202.245,97.212 202.753,97.212 ; 202.245,97.216 202.245,97.724 ; 202.245,97.216 202.753,97.216 ; 202.245,97.724 202.245,98.232 ; 202.245,97.724 202.753,97.724 ; 202.245,98.232 202.245,98.74 ; 202.245,98.232 202.753,98.232 ; 202.245,98.74 202.245,99.248 ; 202.245,98.74 202.753,98.74 ; 202.245,99.248 202.245,99.756 ; 202.245,99.248 202.753,99.248 ; 202.245,99.756 202.245,100.264 ; 202.245,99.756 202.753,99.756 ; 202.245,100.264 202.245,100.772 ; 202.245,100.264 202.753,100.264 ; 202.245,100.772 202.245,101.28 ; 202.245,100.772 202.753,100.772 ; 202.245,101.28 202.245,101.788 ; 202.245,101.28 202.753,101.28 ; 202.245,101.788 202.245,102.296 ; 202.245,101.788 202.753,101.788 ; 202.245,102.296 202.245,102.804 ; 202.245,102.296 202.753,102.296 ; 202.245,102.804 202.245,103.312 ; 202.245,102.804 202.753,102.804 ; 202.245,103.312 202.245,103.82 ; 202.245,103.312 202.753,103.312 ; 202.245,103.82 202.245,104.107 ; 202.245,103.82 202.753,103.82 ; 202.245,104.107 202.753,104.107 ; 202.753,97.212 202.753,97.216 ; 202.753,97.212 203.261,97.212 ; 202.753,97.216 202.753,97.724 ; 202.753,97.216 203.261,97.216 ; 202.753,97.724 202.753,98.232 ; 202.753,97.724 203.261,97.724 ; 202.753,98.232 202.753,98.74 ; 202.753,98.232 203.261,98.232 ; 202.753,98.74 202.753,99.248 ; 202.753,98.74 203.261,98.74 ; 202.753,99.248 202.753,99.756 ; 202.753,99.248 203.261,99.248 ; 202.753,99.756 202.753,100.264 ; 202.753,99.756 203.261,99.756 ; 202.753,100.264 202.753,100.772 ; 202.753,100.264 203.261,100.264 ; 202.753,100.772 202.753,101.28 ; 202.753,100.772 203.261,100.772 ; 202.753,101.28 202.753,101.788 ; 202.753,101.28 203.261,101.28 ; 202.753,101.788 202.753,102.296 ; 202.753,101.788 203.261,101.788 ; 202.753,102.296 202.753,102.804 ; 202.753,102.296 203.261,102.296 ; 202.753,102.804 202.753,103.312 ; 202.753,102.804 203.261,102.804 ; 202.753,103.312 202.753,103.82 ; 202.753,103.312 203.261,103.312 ; 202.753,103.82 202.753,104.107 ; 202.753,103.82 203.261,103.82 ; 202.753,104.107 203.261,104.107 ; 203.261,97.212 203.261,97.216 ; 203.261,97.212 203.769,97.212 ; 203.261,97.216 203.261,97.724 ; 203.261,97.216 203.769,97.216 ; 203.261,97.724 203.261,98.232 ; 203.261,97.724 203.769,97.724 ; 203.261,98.232 203.261,98.74 ; 203.261,98.232 203.769,98.232 ; 203.261,98.74 203.261,99.248 ; 203.261,98.74 203.769,98.74 ; 203.261,99.248 203.261,99.756 ; 203.261,99.248 203.769,99.248 ; 203.261,99.756 203.261,100.264 ; 203.261,99.756 203.769,99.756 ; 203.261,100.264 203.261,100.772 ; 203.261,100.264 203.769,100.264 ; 203.261,100.772 203.261,101.28 ; 203.261,100.772 203.769,100.772 ; 203.261,101.28 203.261,101.788 ; 203.261,101.28 203.769,101.28 ; 203.261,101.788 203.261,102.296 ; 203.261,101.788 203.769,101.788 ; 203.261,102.296 203.261,102.804 ; 203.261,102.296 203.769,102.296 ; 203.261,102.804 203.261,103.312 ; 203.261,102.804 203.769,102.804 ; 203.261,103.312 203.261,103.82 ; 203.261,103.312 203.769,103.312 ; 203.261,103.82 203.261,104.107 ; 203.261,103.82 203.769,103.82 ; 203.261,104.107 203.769,104.107 ; 203.769,97.212 203.769,97.216 ; 203.769,97.212 204.277,97.212 ; 203.769,97.216 203.769,97.724 ; 203.769,97.216 204.277,97.216 ; 203.769,97.724 203.769,98.232 ; 203.769,97.724 204.277,97.724 ; 203.769,98.232 203.769,98.74 ; 203.769,98.232 204.277,98.232 ; 203.769,98.74 203.769,99.248 ; 203.769,98.74 204.277,98.74 ; 203.769,99.248 203.769,99.756 ; 203.769,99.248 204.277,99.248 ; 203.769,99.756 203.769,100.264 ; 203.769,99.756 204.277,99.756 ; 203.769,100.264 203.769,100.772 ; 203.769,100.264 204.277,100.264 ; 203.769,100.772 203.769,101.28 ; 203.769,100.772 204.277,100.772 ; 203.769,101.28 203.769,101.788 ; 203.769,101.28 204.277,101.28 ; 203.769,101.788 203.769,102.296 ; 203.769,101.788 204.277,101.788 ; 203.769,102.296 203.769,102.804 ; 203.769,102.296 204.277,102.296 ; 203.769,102.804 203.769,103.312 ; 203.769,102.804 204.277,102.804 ; 203.769,103.312 203.769,103.82 ; 203.769,103.312 204.277,103.312 ; 203.769,103.82 203.769,104.107 ; 203.769,103.82 204.277,103.82 ; 203.769,104.107 204.277,104.107 ; 204.277,97.212 204.277,97.216 ; 204.277,97.212 204.785,97.212 ; 204.277,97.216 204.277,97.724 ; 204.277,97.216 204.785,97.216 ; 204.277,97.724 204.277,98.232 ; 204.277,97.724 204.785,97.724 ; 204.277,98.232 204.277,98.74 ; 204.277,98.232 204.785,98.232 ; 204.277,98.74 204.277,99.248 ; 204.277,98.74 204.785,98.74 ; 204.277,99.248 204.277,99.756 ; 204.277,99.248 204.785,99.248 ; 204.277,99.756 204.277,100.264 ; 204.277,99.756 204.785,99.756 ; 204.277,100.264 204.277,100.772 ; 204.277,100.264 204.785,100.264 ; 204.277,100.772 204.277,101.28 ; 204.277,100.772 204.785,100.772 ; 204.277,101.28 204.277,101.788 ; 204.277,101.28 204.785,101.28 ; 204.277,101.788 204.277,102.296 ; 204.277,101.788 204.785,101.788 ; 204.277,102.296 204.277,102.804 ; 204.277,102.296 204.785,102.296 ; 204.277,102.804 204.277,103.312 ; 204.277,102.804 204.785,102.804 ; 204.277,103.312 204.277,103.82 ; 204.277,103.312 204.785,103.312 ; 204.277,103.82 204.277,104.107 ; 204.277,103.82 204.785,103.82 ; 204.277,104.107 204.785,104.107 ; 204.785,97.212 204.785,97.216 ; 204.785,97.212 205.293,97.212 ; 204.785,97.216 204.785,97.724 ; 204.785,97.216 205.293,97.216 ; 204.785,97.724 204.785,98.232 ; 204.785,97.724 205.293,97.724 ; 204.785,98.232 204.785,98.74 ; 204.785,98.232 205.293,98.232 ; 204.785,98.74 204.785,99.248 ; 204.785,98.74 205.293,98.74 ; 204.785,99.248 204.785,99.756 ; 204.785,99.248 205.293,99.248 ; 204.785,99.756 204.785,100.264 ; 204.785,99.756 205.293,99.756 ; 204.785,100.264 204.785,100.772 ; 204.785,100.264 205.293,100.264 ; 204.785,100.772 204.785,101.28 ; 204.785,100.772 205.293,100.772 ; 204.785,101.28 204.785,101.788 ; 204.785,101.28 205.293,101.28 ; 204.785,101.788 204.785,102.296 ; 204.785,101.788 205.293,101.788 ; 204.785,102.296 204.785,102.804 ; 204.785,102.296 205.293,102.296 ; 204.785,102.804 204.785,103.312 ; 204.785,102.804 205.293,102.804 ; 204.785,103.312 204.785,103.82 ; 204.785,103.312 205.293,103.312 ; 204.785,103.82 204.785,104.107 ; 204.785,103.82 205.293,103.82 ; 204.785,104.107 205.293,104.107 ; 205.293,97.212 205.293,97.216 ; 205.293,97.212 205.801,97.212 ; 205.293,97.216 205.293,97.724 ; 205.293,97.216 205.801,97.216 ; 205.293,97.724 205.293,98.232 ; 205.293,97.724 205.801,97.724 ; 205.293,98.232 205.293,98.74 ; 205.293,98.232 205.801,98.232 ; 205.293,98.74 205.293,99.248 ; 205.293,98.74 205.801,98.74 ; 205.293,99.248 205.293,99.756 ; 205.293,99.248 205.801,99.248 ; 205.293,99.756 205.293,100.264 ; 205.293,99.756 205.801,99.756 ; 205.293,100.264 205.293,100.772 ; 205.293,100.264 205.801,100.264 ; 205.293,100.772 205.293,101.28 ; 205.293,100.772 205.801,100.772 ; 205.293,101.28 205.293,101.788 ; 205.293,101.28 pad.@205.801,101.28 ; 205.293,101.788 205.293,102.296 ; 205.293,101.788 205.801,101.788 ; 205.293,102.296 205.293,102.804 ; 205.293,102.296 205.801,102.296 ; 205.293,102.804 205.293,103.312 ; 205.293,102.804 205.801,102.804 ; 205.293,103.312 205.293,103.82 ; 205.293,103.312 205.801,103.312 ; 205.293,103.82 205.293,104.107 ; 205.293,103.82 205.801,103.82 ; 205.293,104.107 205.801,104.107 ; 205.801,97.212 205.801,97.216 ; 205.801,97.212 206.309,97.212 ; 205.801,97.216 205.801,97.724 ; 205.801,97.216 206.309,97.216 ; 205.801,97.724 205.801,98.232 ; 205.801,97.724 206.309,97.724 ; 205.801,98.232 205.801,98.74 ; 205.801,98.232 206.309,98.232 ; 205.801,98.74 205.801,99.248 ; 205.801,98.74 206.309,98.74 ; 205.801,99.248 205.801,99.756 ; 205.801,99.248 206.309,99.248 ; 205.801,99.756 205.801,100.264 ; 205.801,99.756 206.309,99.756 ; 205.801,100.264 205.801,100.772 ; 205.801,100.264 206.309,100.264 ; 205.801,100.772 206.309,100.772 ; 205.801,100.772 pad.@205.801,101.28 ; pad.@205.801,101.28 205.801,101.788 ; pad.@205.801,101.28 206.309,101.28 ; 205.801,101.788 205.801,102.296 ; 205.801,101.788 206.309,101.788 ; 205.801,102.296 205.801,102.804 ; 205.801,102.296 206.309,102.296 ; 205.801,102.804 205.801,103.312 ; 205.801,102.804 206.309,102.804 ; 205.801,103.312 205.801,103.82 ; 205.801,103.312 206.309,103.312 ; 205.801,103.82 205.801,104.107 ; 205.801,103.82 206.309,103.82 ; 205.801,104.107 206.309,104.107 ; 206.309,97.212 206.309,97.216 ; 206.309,97.212 206.817,97.212 ; 206.309,97.216 206.309,97.724 ; 206.309,97.216 206.817,97.216 ; 206.309,97.724 206.309,98.232 ; 206.309,97.724 206.817,97.724 ; 206.309,98.232 206.309,98.74 ; 206.309,98.232 206.817,98.232 ; 206.309,98.74 206.309,99.248 ; 206.309,98.74 206.817,98.74 ; 206.309,99.248 206.309,99.756 ; 206.309,99.248 206.817,99.248 ; 206.309,99.756 206.309,100.264 ; 206.309,99.756 206.817,99.756 ; 206.309,100.264 206.309,100.772 ; 206.309,100.264 206.817,100.264 ; 206.309,100.772 206.817,100.772 ; 206.309,100.772 206.309,101.28 ; 206.309,101.28 206.309,101.788 ; 206.309,101.28 206.817,101.28 ; 206.309,101.788 206.309,102.296 ; 206.309,101.788 206.817,101.788 ; 206.309,102.296 206.309,102.804 ; 206.309,102.296 206.817,102.296 ; 206.309,102.804 206.309,103.312 ; 206.309,102.804 206.817,102.804 ; 206.309,103.312 206.309,103.82 ; 206.309,103.312 206.817,103.312 ; 206.309,103.82 206.309,104.107 ; 206.309,103.82 206.817,103.82 ; 206.309,104.107 206.817,104.107 ; 206.817,97.212 206.817,97.216 ; 206.817,97.212 207.325,97.212 ; 206.817,97.216 206.817,97.724 ; 206.817,97.216 207.325,97.216 ; 206.817,97.724 206.817,98.232 ; 206.817,97.724 207.325,97.724 ; 206.817,98.232 206.817,98.74 ; 206.817,98.232 207.325,98.232 ; 206.817,98.74 206.817,99.248 ; 206.817,98.74 207.325,98.74 ; 206.817,99.248 206.817,99.756 ; 206.817,99.248 207.325,99.248 ; 206.817,99.756 206.817,100.264 ; 206.817,99.756 207.325,99.756 ; 206.817,100.264 206.817,100.772 ; 206.817,100.264 207.325,100.264 ; 206.817,100.772 206.817,101.28 ; 206.817,100.772 207.325,100.772 ; 206.817,101.28 206.817,101.788 ; 206.817,101.28 207.325,101.28 ; 206.817,101.788 206.817,102.296 ; 206.817,101.788 207.325,101.788 ; 206.817,102.296 206.817,102.804 ; 206.817,102.296 207.325,102.296 ; 206.817,102.804 206.817,103.312 ; 206.817,102.804 207.325,102.804 ; 206.817,103.312 206.817,103.82 ; 206.817,103.312 207.325,103.312 ; 206.817,103.82 206.817,104.107 ; 206.817,103.82 207.325,103.82 ; 206.817,104.107 207.325,104.107 ; 207.325,97.212 207.325,97.216 ; 207.325,97.212 207.833,97.212 ; 207.325,97.216 207.325,97.724 ; 207.325,97.216 207.833,97.216 ; 207.325,97.724 207.325,98.232 ; 207.325,97.724 207.833,97.724 ; 207.325,98.232 207.325,98.74 ; 207.325,98.232 207.833,98.232 ; 207.325,98.74 207.325,99.248 ; 207.325,98.74 207.833,98.74 ; 207.325,99.248 207.325,99.756 ; 207.325,99.248 207.833,99.248 ; 207.325,99.756 207.325,100.264 ; 207.325,99.756 207.833,99.756 ; 207.325,100.264 207.325,100.772 ; 207.325,100.264 207.833,100.264 ; 207.325,100.772 207.325,101.28 ; 207.325,100.772 207.833,100.772 ; 207.325,101.28 207.325,101.788 ; 207.325,101.28 207.833,101.28 ; 207.325,101.788 207.325,102.296 ; 207.325,101.788 207.833,101.788 ; 207.325,102.296 207.325,102.804 ; 207.325,102.296 207.833,102.296 ; 207.325,102.804 207.325,103.312 ; 207.325,102.804 207.833,102.804 ; 207.325,103.312 207.325,103.82 ; 207.325,103.312 207.833,103.312 ; 207.325,103.82 207.325,104.107 ; 207.325,103.82 207.833,103.82 ; 207.325,104.107 207.833,104.107 ; 207.833,97.212 207.833,97.216 ; 207.833,97.212 208.341,97.212 ; 207.833,97.216 207.833,97.724 ; 207.833,97.216 208.341,97.216 ; 207.833,97.724 207.833,98.232 ; 207.833,97.724 208.341,97.724 ; 207.833,98.232 207.833,98.74 ; 207.833,98.232 208.341,98.232 ; 207.833,98.74 207.833,99.248 ; 207.833,98.74 208.341,98.74 ; 207.833,99.248 207.833,99.756 ; 207.833,99.248 208.341,99.248 ; 207.833,99.756 207.833,100.264 ; 207.833,99.756 208.341,99.756 ; 207.833,100.264 207.833,100.772 ; 207.833,100.264 208.341,100.264 ; 207.833,100.772 207.833,101.28 ; 207.833,100.772 208.341,100.772 ; 207.833,101.28 207.833,101.788 ; 207.833,101.28 208.341,101.28 ; 207.833,101.788 207.833,102.296 ; 207.833,101.788 208.341,101.788 ; 207.833,102.296 207.833,102.804 ; 207.833,102.296 208.341,102.296 ; 207.833,102.804 207.833,103.312 ; 207.833,102.804 208.341,102.804 ; 207.833,103.312 207.833,103.82 ; 207.833,103.312 208.341,103.312 ; 207.833,103.82 207.833,104.107 ; 207.833,103.82 208.341,103.82 ; 207.833,104.107 208.341,104.107 ; 208.341,97.212 208.341,97.216 ; 208.341,97.212 208.849,97.212 ; 208.341,97.216 208.341,97.724 ; 208.341,97.216 208.849,97.216 ; 208.341,97.724 208.341,98.232 ; 208.341,97.724 208.849,97.724 ; 208.341,98.232 208.341,98.74 ; 208.341,98.232 208.849,98.232 ; 208.341,98.74 208.341,99.248 ; 208.341,98.74 208.849,98.74 ; 208.341,99.248 208.341,99.756 ; 208.341,99.248 208.849,99.248 ; 208.341,99.756 208.341,100.264 ; 208.341,99.756 208.849,99.756 ; 208.341,100.264 208.341,100.772 ; 208.341,100.264 208.849,100.264 ; 208.341,100.772 208.341,101.28 ; 208.341,100.772 208.849,100.772 ; 208.341,101.28 208.341,101.788 ; 208.341,101.28 208.849,101.28 ; 208.341,101.788 208.341,102.296 ; 208.341,101.788 208.849,101.788 ; 208.341,102.296 208.341,102.804 ; 208.341,102.296 208.849,102.296 ; 208.341,102.804 208.341,103.312 ; 208.341,102.804 208.849,102.804 ; 208.341,103.312 208.341,103.82 ; 208.341,103.312 208.849,103.312 ; 208.341,103.82 208.341,104.107 ; 208.341,103.82 208.849,103.82 ; 208.341,104.107 208.849,104.107 ; 208.849,97.212 208.849,97.216 ; 208.849,97.212 209.357,97.212 ; 208.849,97.216 208.849,97.724 ; 208.849,97.216 209.357,97.216 ; 208.849,97.724 208.849,98.232 ; 208.849,97.724 209.357,97.724 ; 208.849,98.232 208.849,98.74 ; 208.849,98.232 209.357,98.232 ; 208.849,98.74 208.849,99.248 ; 208.849,98.74 209.357,98.74 ; 208.849,99.248 208.849,99.756 ; 208.849,99.248 209.357,99.248 ; 208.849,99.756 208.849,100.264 ; 208.849,99.756 209.357,99.756 ; 208.849,100.264 208.849,100.772 ; 208.849,100.264 209.357,100.264 ; 208.849,100.772 208.849,101.28 ; 208.849,100.772 209.357,100.772 ; 208.849,101.28 208.849,101.788 ; 208.849,101.28 209.357,101.28 ; 208.849,101.788 208.849,102.296 ; 208.849,101.788 209.357,101.788 ; 208.849,102.296 208.849,102.804 ; 208.849,102.296 209.357,102.296 ; 208.849,102.804 208.849,103.312 ; 208.849,102.804 209.357,102.804 ; 208.849,103.312 208.849,103.82 ; 208.849,103.312 209.357,103.312 ; 208.849,103.82 208.849,104.107 ; 208.849,103.82 209.357,103.82 ; 208.849,104.107 209.357,104.107 ; 209.357,97.212 209.357,97.216 ; 209.357,97.212 pad.@209.865,97.212 ; 209.357,97.216 209.357,97.724 ; 209.357,97.216 pad.@209.865,97.216 ; 209.357,97.724 209.357,98.232 ; 209.357,97.724 pad.@209.865,97.724 ; 209.357,98.232 209.357,98.74 ; 209.357,98.232 209.865,98.232 ; 209.357,98.74 209.357,99.248 ; 209.357,98.74 209.865,98.74 ; 209.357,99.248 209.357,99.756 ; 209.357,99.248 209.865,99.248 ; 209.357,99.756 209.357,100.264 ; 209.357,99.756 209.865,99.756 ; 209.357,100.264 209.357,100.772 ; 209.357,100.264 209.865,100.264 ; 209.357,100.772 209.357,101.28 ; 209.357,100.772 209.865,100.772 ; 209.357,101.28 209.357,101.788 ; 209.357,101.28 pad.@209.865,101.28 ; 209.357,101.788 209.357,102.296 ; 209.357,101.788 209.865,101.788 ; 209.357,102.296 209.357,102.804 ; 209.357,102.296 209.865,102.296 ; 209.357,102.804 209.357,103.312 ; 209.357,102.804 209.865,102.804 ; 209.357,103.312 209.357,103.82 ; 209.357,103.312 209.865,103.312 ; 209.357,103.82 209.357,104.107 ; 209.357,103.82 209.865,103.82 ; 209.357,104.107 209.865,104.107 ; pad.@209.865,97.212 210.373,97.212 ; pad.@209.865,97.212 pad.@209.865,97.216 ; pad.@209.865,97.216 210.373,97.216 ; pad.@209.865,97.216 pad.@209.865,97.724 ; pad.@209.865,97.724 210.373,97.724 ; pad.@209.865,97.724 209.865,98.232 ; 209.865,98.232 210.373,98.232 ; 209.865,98.232 209.865,98.74 ; 209.865,98.74 210.373,98.74 ; 209.865,98.74 209.865,99.248 ; 209.865,99.248 209.865,99.756 ; 209.865,99.248 210.373,99.248 ; 209.865,99.756 210.373,99.756 ; 209.865,99.756 209.865,100.264 ; 209.865,100.264 209.865,100.772 ; 209.865,100.264 210.373,100.264 ; 209.865,100.772 210.373,100.772 ; 209.865,100.772 pad.@209.865,101.28 ; pad.@209.865,101.28 209.865,101.788 ; pad.@209.865,101.28 210.373,101.28 ; 209.865,101.788 209.865,102.296 ; 209.865,101.788 210.373,101.788 ; 209.865,102.296 210.373,102.296 ; 209.865,102.296 209.865,102.804 ; 209.865,102.804 210.373,102.804 ; 209.865,102.804 209.865,103.312 ; 209.865,103.312 209.865,103.82 ; 209.865,103.312 210.373,103.312 ; 209.865,103.82 209.865,104.107 ; 209.865,103.82 210.373,103.82 ; 209.865,104.107 210.373,104.107 ; 210.373,97.212 210.373,97.216 ; 210.373,97.212 210.881,97.212 ; 210.373,97.216 210.373,97.724 ; 210.373,97.216 210.881,97.216 ; 210.373,97.724 210.373,98.232 ; 210.373,97.724 210.881,97.724 ; 210.373,98.232 210.373,98.74 ; 210.373,98.232 210.881,98.232 ; 210.373,98.74 210.881,98.74 ; 210.373,98.74 210.373,99.248 ; 210.373,99.248 210.373,99.756 ; 210.373,99.248 210.881,99.248 ; 210.373,99.756 210.881,99.756 ; 210.373,99.756 210.373,100.264 ; 210.373,100.264 210.373,100.772 ; 210.373,100.264 210.881,100.264 ; 210.373,100.772 210.881,100.772 ; 210.373,100.772 210.373,101.28 ; 210.373,101.28 210.373,101.788 ; 210.373,101.28 210.881,101.28 ; 210.373,101.788 210.373,102.296 ; 210.373,101.788 210.881,101.788 ; 210.373,102.296 210.373,102.804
